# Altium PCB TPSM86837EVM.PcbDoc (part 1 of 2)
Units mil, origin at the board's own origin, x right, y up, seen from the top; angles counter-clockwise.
Board outline 3000 x 2500 mil, 4 copper layers (Top Layer, Signal Layer 1, Signal Layer 2, Bottom Layer), stack 61.2 mil thick; 63 components, 16 nets, 100 pads, 288 vias.
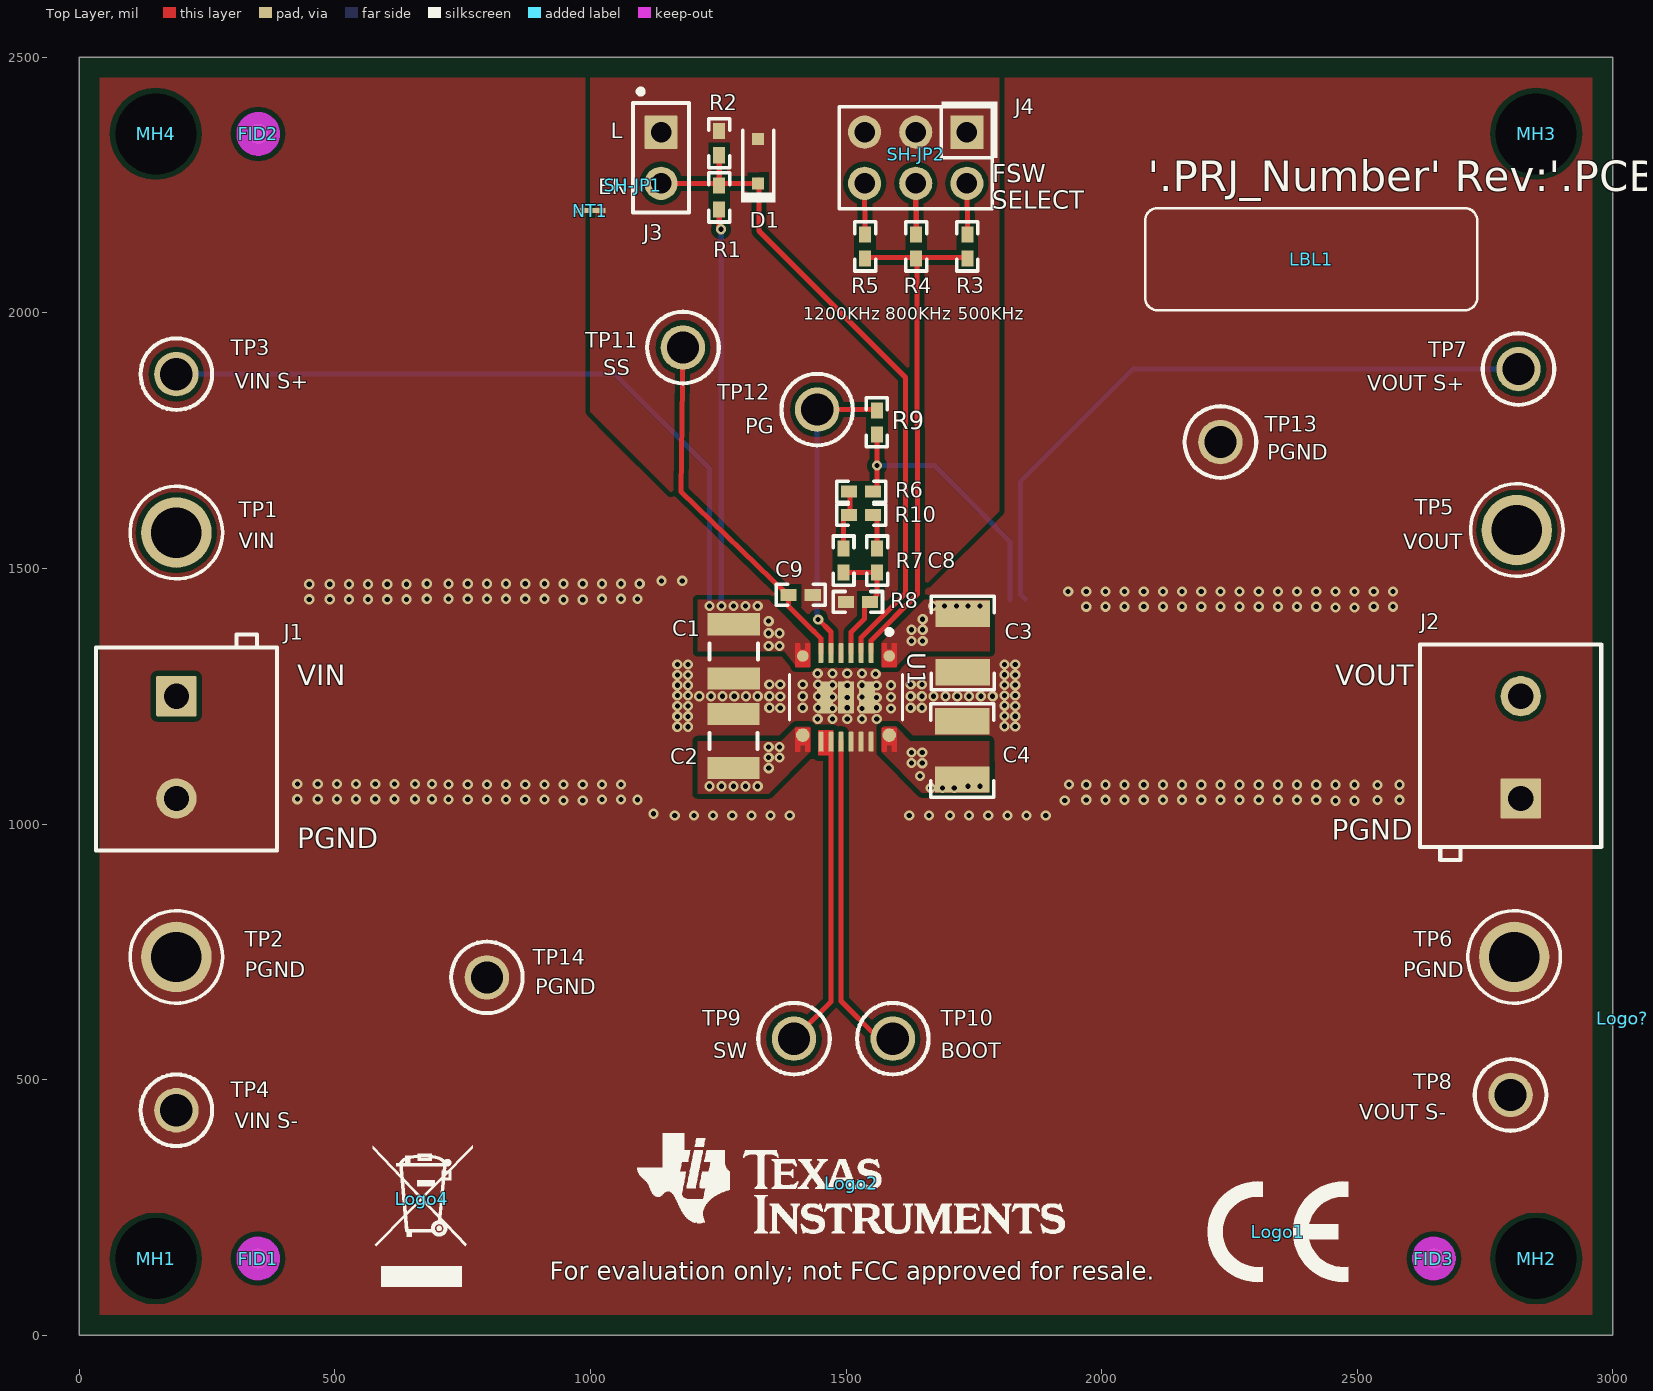
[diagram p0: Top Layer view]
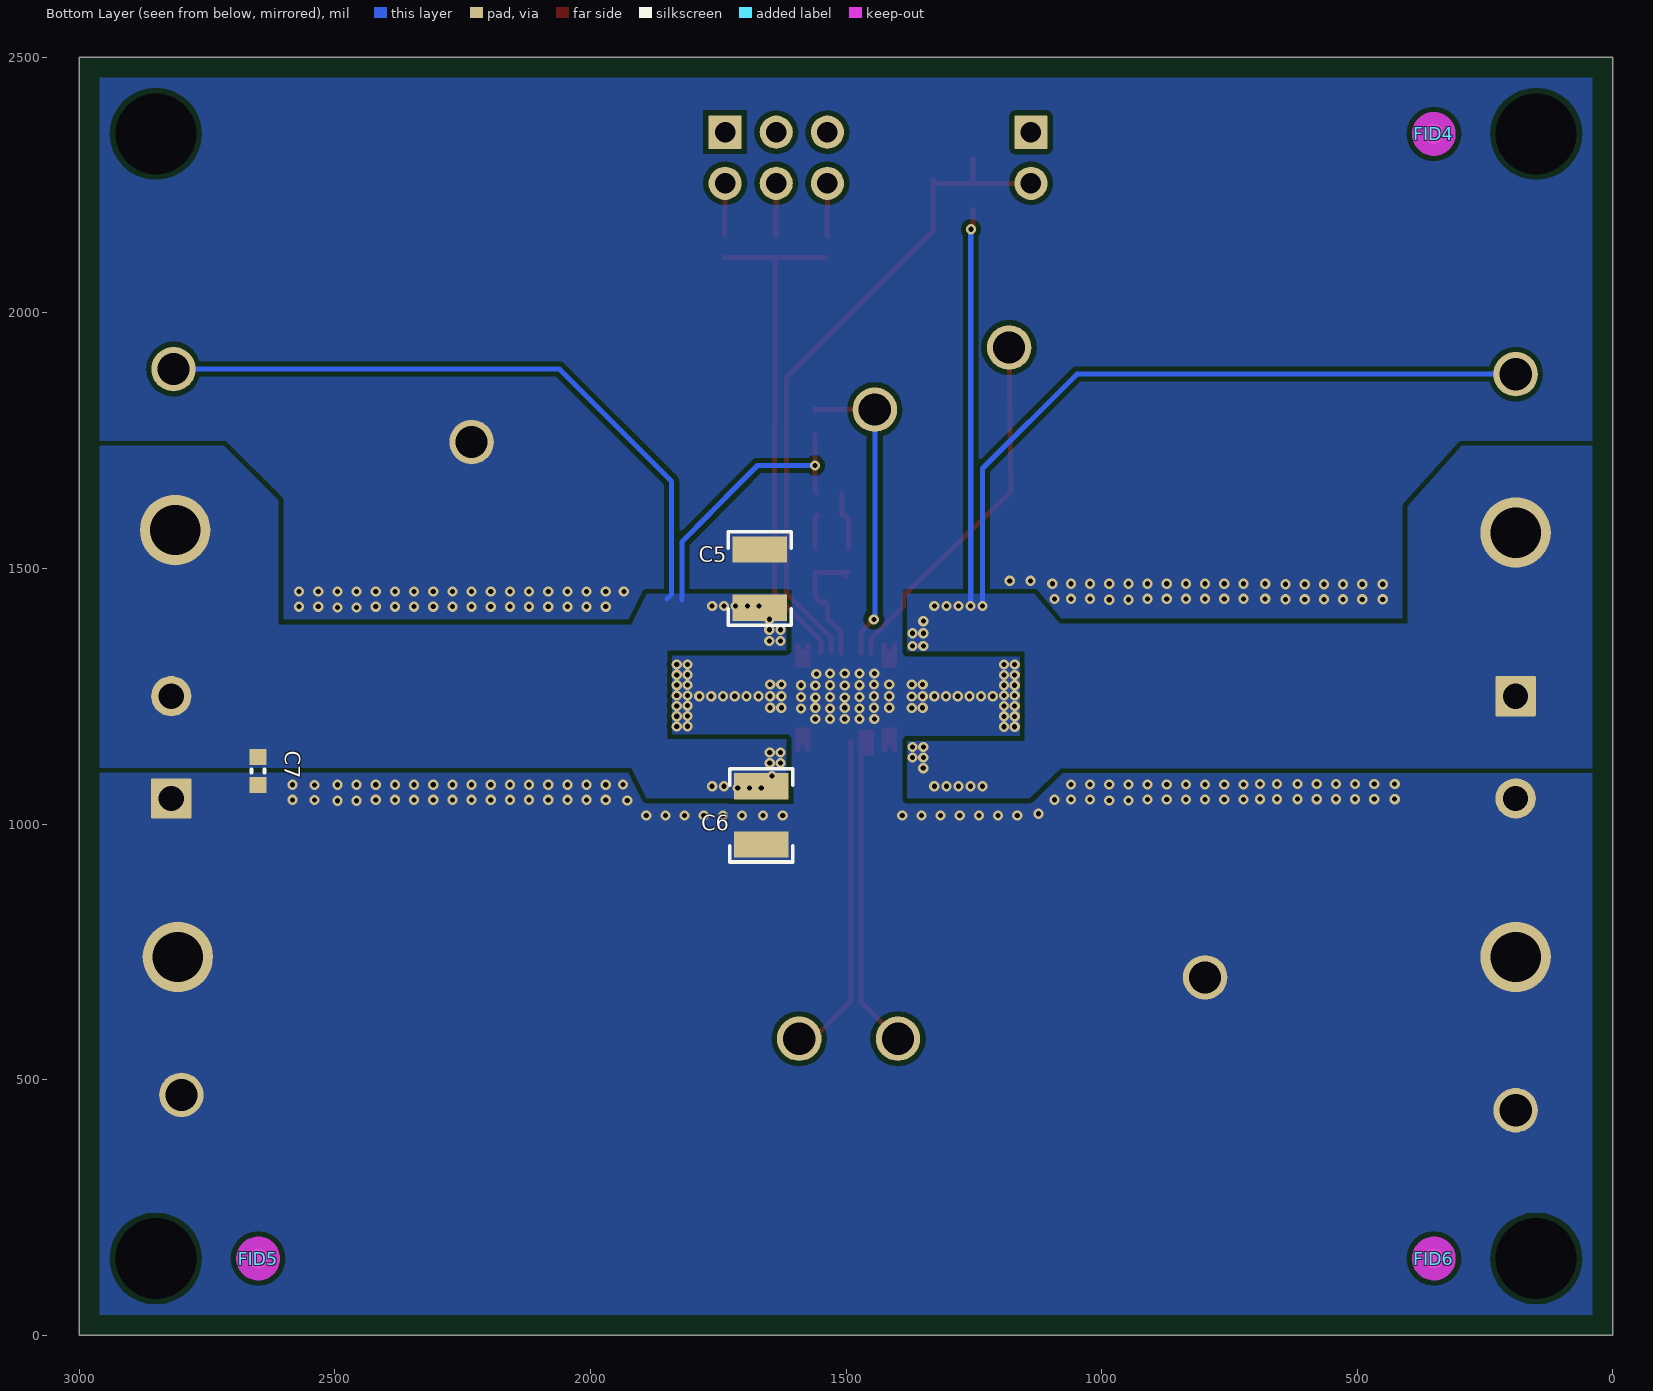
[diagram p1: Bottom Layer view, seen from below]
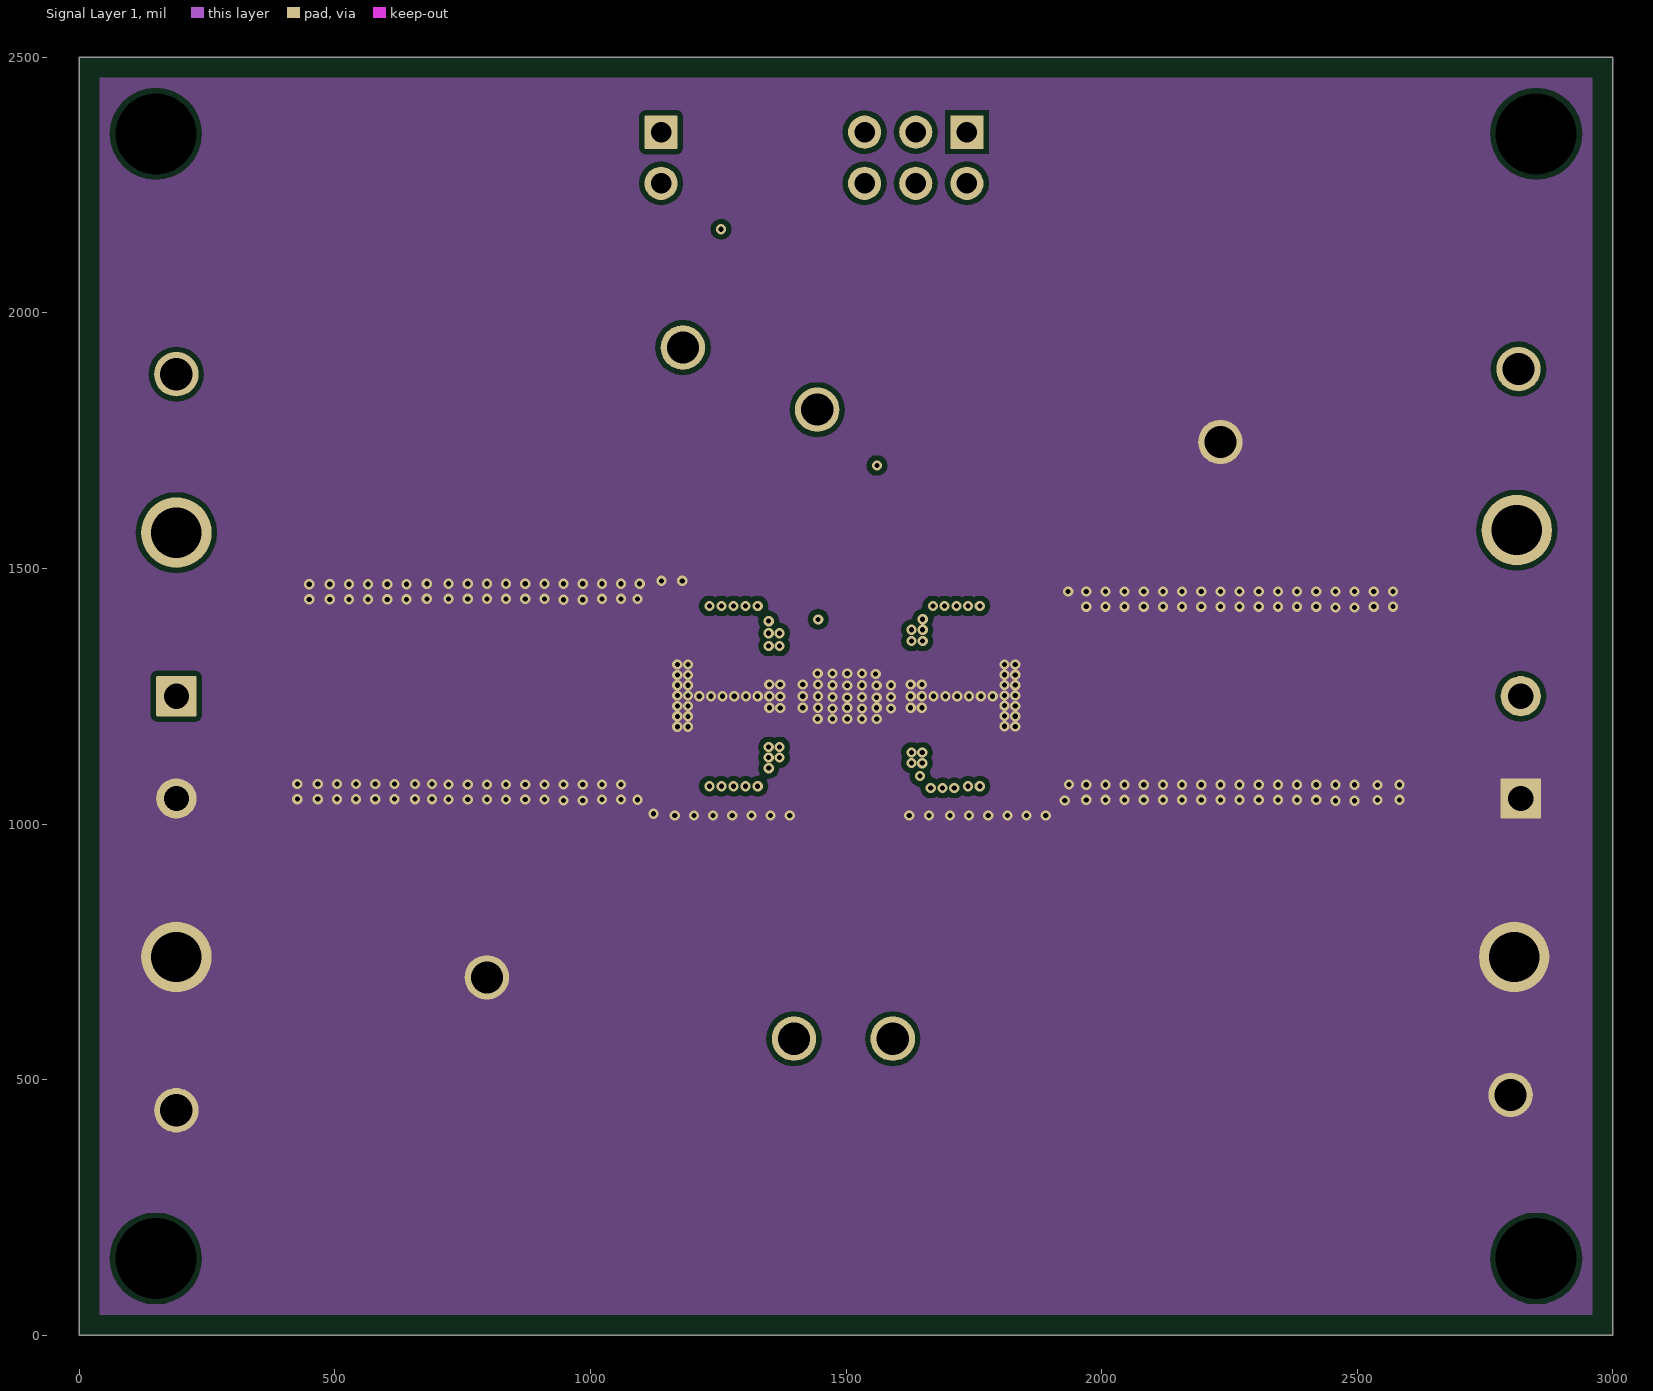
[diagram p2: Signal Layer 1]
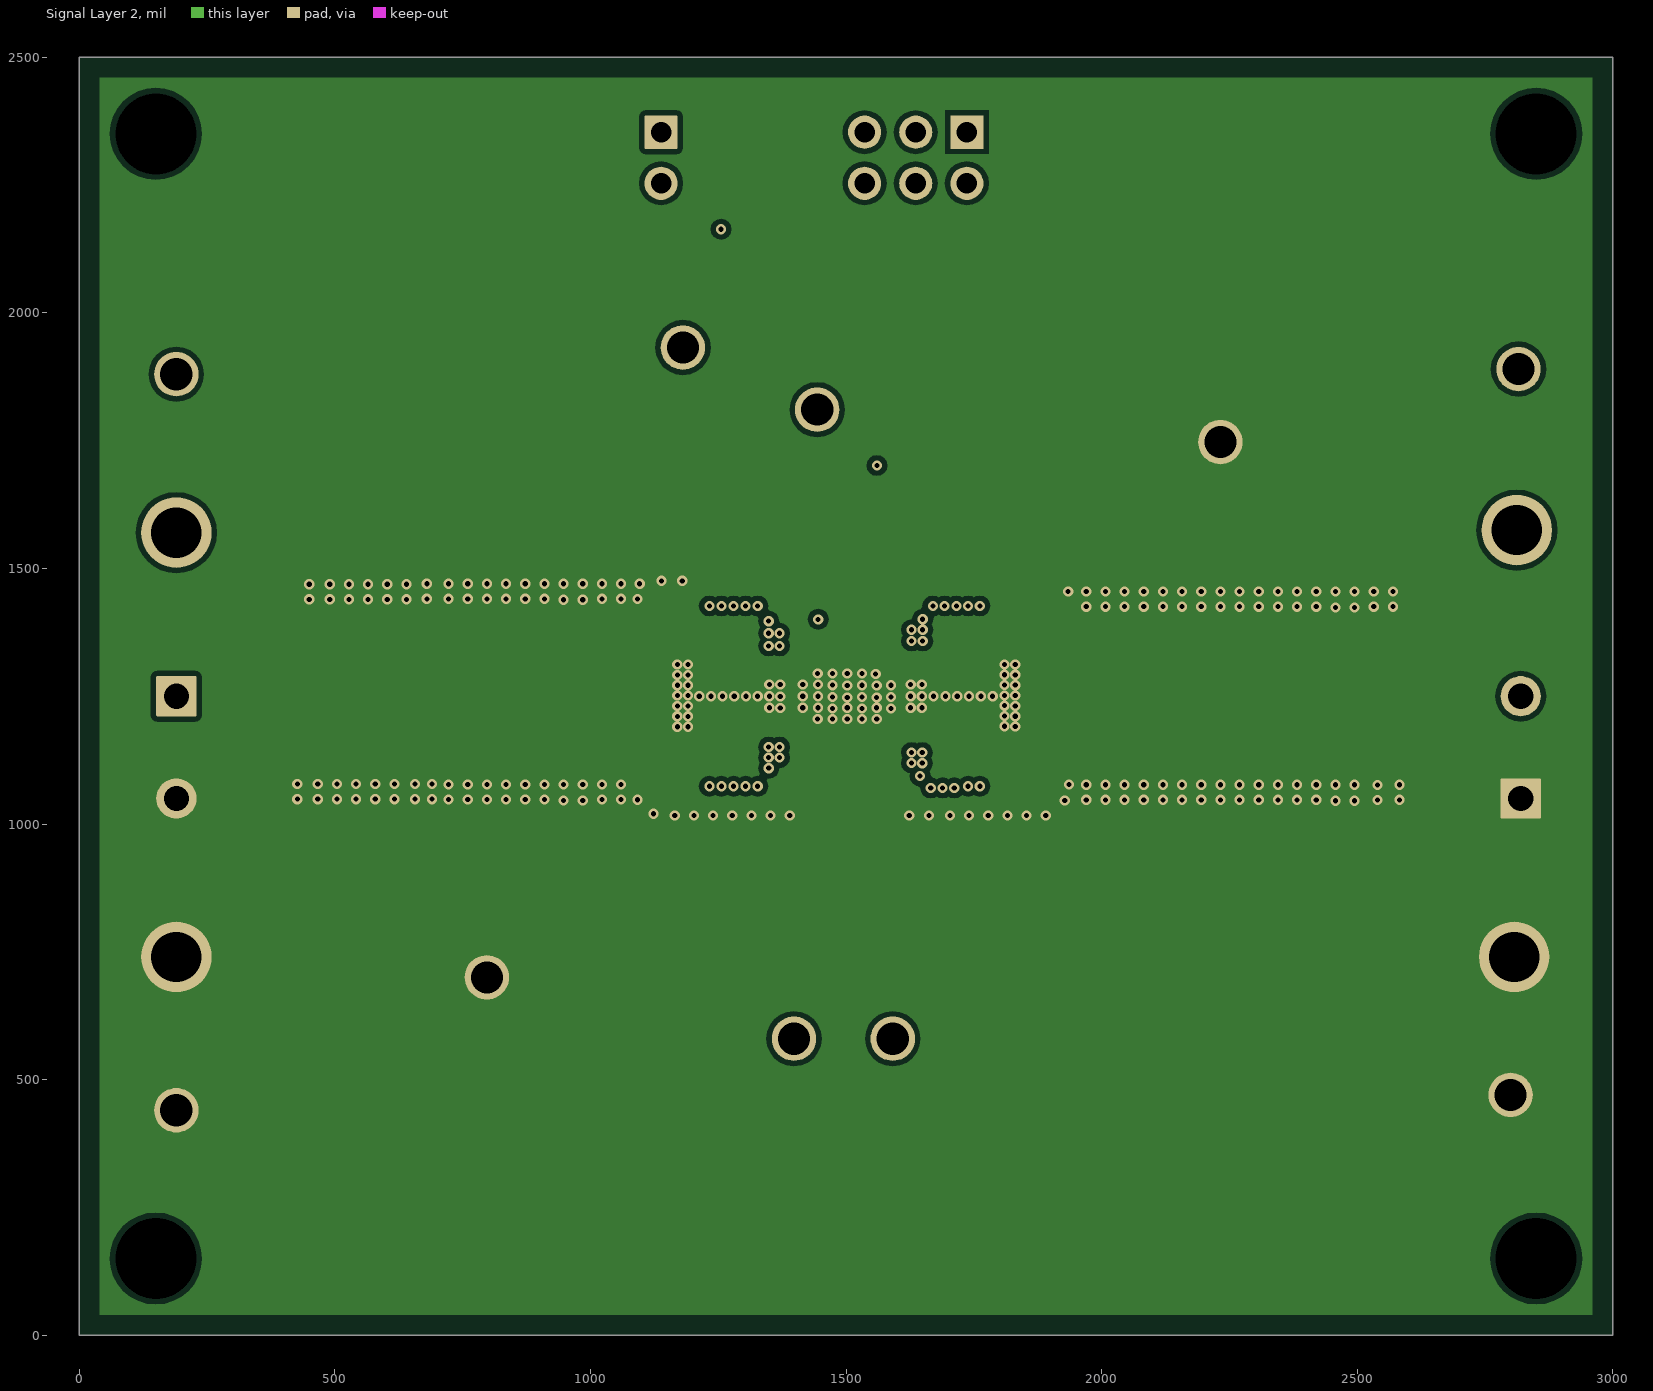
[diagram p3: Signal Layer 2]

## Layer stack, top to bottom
Top Solder: solder mask 0.4, Solder Resist, Dk 3.5
Top Layer: signal copper 2.8
Dielectric1: core 5, FR-4 High Tg, Dk 4.8
Signal Layer 1: signal copper 2.8
Dielectric3: dielectric 40, FR-4 High Tg, Dk 4.8
Signal Layer 2: signal copper 2.8
Dielectric2: dielectric 5, FR-4 High Tg, Dk 4.8
Bottom Layer: signal copper 2.8
Bottom Solder: solder mask 0.4, Solder Resist, Dk 3.5

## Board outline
0,0 3000,0 3000,2500 0,2500

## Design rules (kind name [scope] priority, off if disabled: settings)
AcuteAngle [All] p1: minimum=1.50000000000000E+0001 checktracksonly=FALSE
AssemblyTestPointUsage [All] p1: valid=2
BoardOutlineClearance BoardOutlineClearance_MountingHoles [OnCopper and InComponentClass('Mounting Holes')] p1: gap=39.37 ignorepadtopadclearanceinfootprint=FALSE
BoardOutlineClearance BoardOutlineClearance_Poly [OnCopper and IsPoly] p2: gap=40 ignorepadtopadclearanceinfootprint=FALSE
BoardOutlineClearance [OnCopper and Not InComponentClass('Logo') and not InComponentClass('FiducialMark') and not InRegion(1000,500,4000,800) and not InPoly] p3: gap=50 ignorepadtopadclearanceinfootprint=FALSE
Clearance Clearance_Keepouts [((IsTrack Or IsArc) And Not InPoly) And IsFree and IsKeepOut vs ((IsTrack Or IsArc) And Not InPoly) And IsFree and IsKeepOut] p1: gap=0 ignorepadtopadclearanceinfootprint=FALSE
Clearance Clearance_Poly [InPolygon] p2: gap=10 ignorepadtopadclearanceinfootprint=TRUE
Clearance Clearance_FiducialMark [IsKeepOut and InComponentClass('FiducialMark') vs IsPad and InComponentClass('FiducialMark')] p3: gap=0 ignorepadtopadclearanceinfootprint=FALSE
Clearance [All] p4: gap=7.87 ignorepadtopadclearanceinfootprint=TRUE
ComponentClearance ComponentClearance_MountingHoles_FiducialMarks [InComponentClass('Mounting Holes') vs InComponentClass('FiducialMark')] p1: gap=50 collisioncheckmode=3 verticalgap=10 showdistances=FALSE
ComponentClearance ComponentClearance_Shunt [InComponentClass('Header') vs InComponentClass('Shunt')] p2: gap=0 collisioncheckmode=3 verticalgap=0 showdistances=FALSE
ComponentClearance ComponentClearance_Logo [InComponentClass('Logo')] p3: gap=50 collisioncheckmode=3 verticalgap=10 showdistances=FALSE
ComponentClearance ComponentClearance_ScrewToNut [(HasFootprint('NY PMS 440 0025 PH')) vs (HasFootprint('Keystone_1902C'))] p4: gap=5 collisioncheckmode=3 verticalgap=10 showdistances=FALSE
ComponentClearance ComponentClearance_MountingHoles [InComponentClass('Mounting Holes')] p5: gap=250 collisioncheckmode=3 verticalgap=100000 showdistances=FALSE
ComponentClearance ComponentClearance_SmallPassives [HasFootprint('0201*') or HasFootprint('0402*') or HasFootprint('0508') or HasFootprint('0603*') or HasFootprint('0612') or HasFootprint('0805*') or HasFootprint('0815*') or HasFootprint('0830*') or HasFootprint('1206*') or HasFootprint('1210*') or HasFootprint('1808*') or HasFootprint('1812*') or HasFootprint('1825*') or HasFootprint('2010*') or HasFootprint('2220*') or HasFootprint('2225*') or HasFootprint('2512*') or HasFootprint('2728*') or HasFootprint('3518*') vs HasFootprint('0201*') or HasFootprint('0402*') or HasFootprint('0508') or HasFootprint('0603*') or HasFootprint('0612') or HasFootprint('0805*') or HasFootprint('0815*') or HasFootprint('0830*') or HasFootprint('1206*') or HasFootprint('1210*') or HasFootprint('1808*') or HasFootprint('1812*') or HasFootprint('1825*') or HasFootprint('2010*') or HasFootprint('2220*') or HasFootprint('2225*') or HasFootprint('2512*') or HasFootprint('2728*') or HasFootprint('3518*')] p6: gap=14.96 collisioncheckmode=3 verticalgap=10 showdistances=FALSE
ComponentClearance ComponentClearance_THtoSMT [IsThruComponent vs IsSMTComponent] p7: gap=40 collisioncheckmode=3 verticalgap=30 showdistances=FALSE
ComponentClearance ComponentClearance_THtoTH [IsThruComponent vs IsThruComponent] p8: gap=30 collisioncheckmode=3 verticalgap=30 showdistances=FALSE
ComponentClearance ComponentClearance_NetTie [HasFootprint('Net-Tie_10milWide_30milLong')] p9: gap=0 collisioncheckmode=3 verticalgap=0 showdistances=FALSE
ComponentClearance [All] p10: gap=15 collisioncheckmode=3 verticalgap=10 showdistances=FALSE
DiffPairsRouting [All] p1: maxlimit=100 minlimit=10 mostfreqgap=10 toplayer_minwidth=15 toplayer_maxwidth=15 toplayer_prefwidth=15 midlayer1_minwidth=15 midlayer1_maxwidth=15 midlayer1_prefwidth=15 midlayer2_minwidth=15 midlayer2_maxwidth=15 midlayer2_prefwidth=15 bottomlayer_minwidth=15 bottomlayer_maxwidth=15 bottomlayer_prefwidth=15 maxuncoupledlength=1000
FabricationTestPointUsage TestPointUsage [All] p1: valid=2 allowmultiple=FALSE
FabricationTestpoint Testpoint [All] p1: side=3 testpointundercomponent=TRUE minsize=40 maxsize=100 preferedsize=60 minholesize=0 maxholesize=40 preferedholesize=32 testpointgrid=1 allowsidetop=TRUE allowsidebottom=TRUE usegrid=TRUE gridtolerance=0.01
FanoutControl Fanout_LCC [IsLCC] p1: bgadir=Out bgaviamode=Centered fanoutstyle=Auto fanoutdirection=Alternating viagrid=1 // Fanout_LCC (Default Rule)
FanoutControl Fanout_BGA [IsBGA] p2: bgadir=Out bgaviamode=Centered fanoutstyle=Auto fanoutdirection=Alternating viagrid=1 // Fanout_BGA (Default Rule)
FanoutControl Fanout_Default [All] p4: bgadir=Out bgaviamode=Centered fanoutstyle=Auto fanoutdirection=Alternating viagrid=1 // Fanout_Default (Default Rule)
FanoutControl Fanout_Small [(CompPinCount < 5)] p5: bgadir=Out bgaviamode=Centered fanoutstyle=Auto fanoutdirection=OutThenIn viagrid=1 // Fanout_Small (Default Rule)
HoleSize [All] p1: absolutevalues=TRUE maxlimit=251 minlimit=7.87 maxpercent=80.000 minpercent=20.000
HoleToHoleClearance [All] p1: gap=0 allowstackedmicrovias=TRUE
MinimumAnnularRing MinimumAnnularRing_ThermalPadVias [IsVia and InAnyComponent] p1: minimumring=5
MinimumAnnularRing [All] p2: minimumring=5
MinimumSolderMaskSliver MinimumSolderMaskSliver_Logo [InComponentClass('Logo') vs InComponentClass('Logo')] p1: minsoldermaskwidth=0.7
MinimumSolderMaskSliver [All] p2: minsoldermaskwidth=0
PlaneConnect [All] p1: planeconnectstyle=Relief reliefexpansion=10 reliefentries=4 reliefconductorwidth=10 reliefairgap=10
PolygonConnect PolygonConnect_TH [IsThruPin] p1: connectstyle=Direct reliefconductorwidth=10 reliefentries=4 polygonreliefangle="90 Angle" airgapwidth=10
PolygonConnect [All] p2: connectstyle=Direct reliefconductorwidth=10 reliefentries=4 polygonreliefangle="90 Angle" airgapwidth=10
RoutingVias ThermalPadVias [IsVia and InAnyComponent] p1: holewidth=7.87 width=19.68 viastyle="Through Hole" minholewidth=7.87 minwidth=19.68 maxholewidth=12.99 maxwidth=23.62
RoutingVias [All] p2: holewidth=10 width=22 viastyle="Through Hole" minholewidth=7.87 minwidth=8 maxholewidth=40 maxwidth=65
SilkToBoardRegionClearance [Not ((IsComment or IsDesignator) And (Hide <> 'False')) and not InRegion(1000,500,4000,800)] p1:
SilkToSilkClearance SilkToSilkClearance_Pb-FreeLogo [(HasFootprint('Pb-Free_Overlay_Medium') OR HasFootprint('Pb-Free_Overlay_Small')) vs (HasFootprint('Pb-Free_Overlay_Medium') OR HasFootprint('Pb-Free_Overlay_Small'))] p1: silktosilkclearance=0
SilkToSilkClearance [All] p2: silktosilkclearance=0
SilkToSolderMaskClearance SilkToComponentPadClearance [(IsPad or IsFill or IsRegion) and InAnycomponent] p1: minsilkscreentomaskgap=0 clearancetoexposedcopper=TRUE
SilkToSolderMaskClearance "Silk to Solder Mask Opening" [All] p2: minsilkscreentomaskgap=0 clearancetoexposedcopper=FALSE
SolderMaskExpansion [All] p1: expansion=1.97 istentingtop=FALSE
UnRoutedNet [All] p1: checkbadconnections=TRUE
Width [All] p1: maxlimit=100 minlimit=6 preferedwidth=10 checkconnectedcopper=TRUE
13 further rules are at their usual default settings.

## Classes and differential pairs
component class Label: LBL1
component class Shunt: SH-JP1 SH-JP2
component class Header: J3 J4
component class TPSM86838EVM: C1 C2 C3 C4 C5 C6 C7 C8 C9 D1 J1 J2 J3 J4 NT1 R1 R2 R3 R4 R5 R6 R7 R8 R9 R10 TP1 TP2 TP3 TP4 TP5 TP6 TP7 TP8 TP9 TP10 TP11 TP12 TP13 TP14 U1
component class TPSM86838EVM_Hardware: !PCB1 FID1 FID2 FID3 FID4 FID5 FID6 H1 H2 H3 H4 H5 H6 H7 H8 LBL1 Logo1 Logo2 Logo4 Logo? MH1 MH2 MH3 MH4 SH-JP1 SH-JP2 ZZ1 ZZ2 ZZ3 ZZ4 ZZ5 ZZ6
component class Logo: Logo2
component class FiducialMark: FID1 FID2 FID3 FID4 FID5 FID6
component class AssemblyNote: ZZ1 ZZ2 ZZ3 ZZ4 ZZ5 ZZ6

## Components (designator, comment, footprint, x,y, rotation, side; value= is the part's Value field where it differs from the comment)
C1 "GRM32ER7YA106KA12L" 1210_270L 1280.34,1337.64 r90 top value=10uF
C2 "GRM32ER7YA106KA12L" 1210_270L 1280,1162.36 r270 top value=10uF
C3 "GRM32ER71E226KE15L" 1210_270 1728.49,1354.09 r270 top value=22uF
C4 "GRM32ER71E226KE15L" 1210_270 1727.37,1143.9 r90 top value=22uF
C5 "GRM32ER71E226KE15L" 1210_270 1668.84,1480.23 r90 bottom value=22uF
C6 "GRM32ER71E226KE15L" 1210_270 1665.68,1016.85 r270 bottom value=22uF
C7 "CGA3E2X7R1E104K080AA" 0603L 2650,1103.89 r270 bottom value=0.1uF
C8 "GRM1555C1H470FA01D" 0402 1561.02,1515.42 r270 top value=47pF
C9 "C1005X7R1H473K050BB" 0402 1411.24,1448.33 r0 top value=0.047uF
D1 "MMSZ5231BS-7-F" SOD-323 1328.16,2296.63 r90 top value=5.1V
FID1 "Fiducial" Fiducial10-20 350,150 r0 top
FID2 "Fiducial" Fiducial10-20 350,2350 r0 top
FID3 "Fiducial" Fiducial10-20 2650,150 r0 top
FID4 "Fiducial" Fiducial10-20 350,2350 r180 bottom
FID5 "Fiducial" Fiducial10-20 2650,150 r180 bottom
FID6 "Fiducial" Fiducial10-20 350,150 r180 bottom
J1 "ED120/2DS" On-Shore_ED120_2DS 190,1150 r270 top
J2 "ED120/2DS" On-Shore_ED120_2DS 2820,1150 r90 top
J3 "EN" TSW-102-07-X-S 1138.16,2303.33 r270 top
J4 "FSW SELECT" SULLINS_PEC03DAAN 1636.47,2303.33 r180 top
LBL1 "THT-14-423-10" Label_650x200 2410,2104.88 r180 top
Logo1 "CE Mark" CE_Mark_5mm 2345,202.26 r0 top
Logo2 "Texas Instruments" TI_Stacked_Overlay_Small 1509.88,296.77 r0 top
Logo4 "WEEE logo" WEEE_Minimum 670,267.32 r0 top
Logo? "FCC disclaimer" FCC_disclaimer 3020,620 r90 top
MH1 "MTG_NoPads" MTG_159mil 150,150 r0 top
MH2 "MTG_NoPads" MTG_159mil 2850,150 r0 top
MH3 "MTG_NoPads" MTG_159mil 2850,2350 r0 top
MH4 "MTG_NoPads" MTG_159mil 150,2350 r0 top
NT1 "Net-Tie" Net-Tie_10milWide_30milLong 1000,2200 r180 top net-tie
R1 "CRCW0402169KFKED" 0402 1251.94,2225.63 r270 top value=169k
R2 "TNPW040236K1BEED" 0402 1251.94,2331.9 r270 top value=36.1k
R3 "RC0402FR-0730K1L" 0402 1737.34,2129.88 r270 top value=30.1k
R4 "CRCW0402162KFKED" 0402 1637.34,2129.88 r270 top value=162k
R5 "CRCW0402374KFKED" 0402 1537.34,2129.88 r270 top value=374k
R6 "RC0402FR-0749R9L" 0402 1529.53,1650.13 r0 top value=49.9
R7 "CRCW040220K0FKED" 0402 1495.19,1515.42 r90 top value=20.0k
R8 "CRCW040210K0FKED" 0402 1523.41,1434.34 r0 top value=10.0k
R9 "RC1005F104CS" 0402 1560.46,1785.6 r270 top value=100k
R10 "CRCW04020000Z0ED" 0402 1529.53,1604.84 r180 top value=0
SH-JP1 "SNT-100-BK-G" SNT-100-BK-G 1083.16,2249.26 r180 top value=1x2
SH-JP2 "SNT-100-BK-G" SNT-100-BK-G 1636.47,2310.48 r90 top value=1x2
TP1 "VIN" Keystone1502-2 190,1570 r0 top
TP2 "PGND" Keystone1502-2 190,740 r0 top
TP3 "VIN S+" Keystone5010 190,1880 r0 top
TP4 "VIN S-" Keystone5011 190,440 r0 top
TP5 "Vout" Keystone1502-2 2812.26,1575 r0 top
TP6 "PGND" Keystone1502-2 2807.11,740 r0 top
TP7 "VOUT S+" Keystone5010 2815.58,1890 r0 top
TP8 "VOUT S-" Keystone5011 2800.04,470 r0 top
TP9 "SW" Keystone5010 1398.27,580 r0 top
TP10 "BOOT" Keystone5010 1591.5,580 r0 top
TP11 "SS" Keystone5010 1181.01,1932.12 r0 top
TP12 "PG" Keystone5010 1443.64,1810.59 r0 top
TP13 "PGND" Keystone5011 2232.5,1747.21 r0 top
TP14 "PGND" Keystone5011 797.5,700 r0 top
U1 "TPSM86837RCGR" RCG0019A-MFG 1500.04,1247.7 r270 top
ZZ1 "This Assembly Note is for PCB labels only" AssemblyNoteLabel 183.32,3180 r0 top
ZZ2 "These assemblies must be clean and free from flux and all contaminants. Use of no clean flux is not acceptable." AssemblyNote 178.91,3089.12 r0 top
ZZ3 "These assemblies must comply with workmanship standards IPC-A-610 Class 2, unless otherwise specified." AssemblyNote 178.91,2996.6 r0 top
ZZ4 "Place SH-J1 on J3 pins 3 and 4" AssemblyNote 178.91,2904.08 r0 top
ZZ5 "Place SH-J2 on J4 pins 5 and 6" AssemblyNote 178.91,2811.56 r0 top
ZZ6 "Place SH-J3 on J5 pins 6 and 7" AssemblyNote 178.91,2719.04 r0 top

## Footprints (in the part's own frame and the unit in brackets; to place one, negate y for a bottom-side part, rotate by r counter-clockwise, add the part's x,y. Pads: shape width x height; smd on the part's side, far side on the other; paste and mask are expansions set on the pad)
0402 [mm] "0402 from SM-752 data"
  rect 0.8x0.6 smd: 1(-0.6,0) 2(0.6,0)
  silkscreen extent -1.22,-0.52 1.22,0.52, body extent -0.55,-0.3 0.55,0.3, height 0.6
0603L [mm] "0603 from SM-752 data"
  rect 0.8x0.85 smd: 1(-0.7,0) 2(0.7,0)
  silkscreen extent -0.07,-0.33 0.07,0.33, body extent -0.87,-0.47 0.87,0.47, height 1
1210_270 [mm] "1210"
  rect 1.3x2.7 smd: 1(-1.45,0) 2(1.45,0)
  silkscreen extent -2.32,-1.57 2.32,1.57, body extent -1.7,-1.35 1.7,1.35, height 2.7
1210_270L [mm] "1210"
  rect 1.1x2.6 smd: 1(-1.35,0) 2(1.35,0)
  silkscreen extent -0.4,-1.2 0.4,1.2, body extent -1.7,-1.35 1.7,1.35, height 2.7
AssemblyNote [mil] "Assembly Note"
AssemblyNoteLabel [mil] "Assembly Note for PCB Labels"
CE_Mark_5mm [mil] "Minimum text height for CE Mark"
  silkscreen extent -138,-98 138,98
FCC_disclaimer [mil]
Fiducial10-20 [mm]
  round 1 smd mask+0.5: 1(0,0)
  Top Layer keep-out circle w1.178: c0,0 r0.5
Keystone1502-2 [mm] "Double Turret"
  round 3.5 hole 2.5: 1(0,0)
  silkscreen extent -2.3,-2.3 2.3,2.3, body extent -1.6,-1.6 1.59,1.6, height 5.62
Keystone5010 [mil] "Keystone Multipurpose loops"
  round 87 hole 63: 1(0,0)
  silkscreen extent -70,-70 70,70, body extent -63,-63 63,62, height 319
Keystone5011 [mil] "Keystone Multipurpose loops"
  round 87 hole 63: 1(0,0)
  silkscreen extent -70,-70 70,70, body extent -63,-63 63,62, height 319
Label_650x200 [mil] "Thermal Transfer Label"
  round 1 on Mech13: 0(0,0)
  silkscreen extent -325,-100 325,100, body extent -325,-100 325,100, height 1
MTG_159mil [mil] "159mil Non Plated Hole"
  round 150 hole 159 unplated: 1(0,0)
Net-Tie_10milWide_30milLong [mil] "10mil net tie, no solder mask opening, no solder paste"
  rect 30x10 smd paste-5 mask-5: 1(-15,0) 2(15,0)
On-Shore_ED120_2DS [mm] "ONSHORE"
  rrect5% 2x2 hole 1.25: 1(-2.54,0)
  round 2 hole 1.25: 2(2.54,0)
  silkscreen extent -5.6,-4 5.12,5, body extent -5.78,-4 5.08,5, height 13
RCG0019A-MFG [mm]
  round 0.573 smd paste-1000 mask+0: 1(-2.057,2.15) 8(-2.057,-2.15)
  rrect40% 1x0.25 smd paste+0 mask+0: 2(-2.2,1.25) 3(-2.2,0.75) 4(-2.2,0.25) 5(-2.2,-0.25) 6(-2.2,-0.75) 7(-2.2,-1.25) 10(2.2,-1.25) 11(2.2,-0.75) 12(2.2,-0.25) 13(2.2,0.25) 14(2.2,0.75) 15(2.2,1.25)
  round 0.675 smd paste-1000 mask+0: 9(1.876,-2.15) 16(1.876,2.15)
  rrect13% 1.6x0.8 smd paste-1000 mask+0: 17(0,1.05) 18(0,0) 19(0,-1.05)
  Top Layer region: -2.65,-2.525 -2.669,-2.521 -2.685,-2.51 -2.696,-2.494 -2.7,-2.475 -2.7,-2.475 -2.7,-2.325 -2.693,-2.3 -2.675,-2.282 -2.65,-2.275 -2.65,-2.275 -2.402,-2.275 -2.385,-2.261 -2.375,-2.241 -2.375,-2.241 -2.375,-2.058 -2.379,-2.041 -2.392,-2.029 -2.408,-2.025 -2.408,-2.025 -2.651,-2.025 -2.67,-2.021 -2.686,-2.01 -2.697,-1.994 -2.701,-1.975 -2.701,-1.975 -2.701,-1.825 -2.694,-1.8 -2.676,-1.782 -2.651,-1.775 -2.651,-1.775 -1.551,-1.775 -1.526,-1.782 -1.508,-1.8 -1.501,-1.825 -1.501,-1.825 -1.501,-2.475 -1.505,-2.494 -1.516,-2.51 -1.532,-2.521 -1.551,-2.525 -1.551,-2.525
  Top Layer region: -2.65,1.775 -2.669,1.779 -2.685,1.79 -2.696,1.806 -2.7,1.825 -2.7,1.825 -2.7,1.975 -2.693,2 -2.675,2.018 -2.65,2.025 -2.65,2.025 -2.402,2.025 -2.385,2.039 -2.375,2.059 -2.375,2.059 -2.375,2.242 -2.379,2.258 -2.392,2.271 -2.408,2.275 -2.408,2.275 -2.651,2.275 -2.67,2.279 -2.686,2.29 -2.697,2.306 -2.701,2.325 -2.701,2.325 -2.701,2.475 -2.694,2.5 -2.676,2.518 -2.651,2.525 -2.651,2.525 -1.551,2.525 -1.526,2.518 -1.508,2.5 -1.501,2.475 -1.501,2.475 -1.501,1.825 -1.505,1.806 -1.516,1.79 -1.532,1.779 -1.551,1.775 -1.551,1.775
  Top Layer region: 2.65,1.775 2.669,1.779 2.685,1.79 2.696,1.806 2.7,1.825 2.7,1.825 2.7,1.975 2.693,2 2.675,2.018 2.65,2.025 2.65,2.025 2.402,2.025 2.385,2.039 2.375,2.059 2.375,2.059 2.375,2.242 2.379,2.258 2.392,2.271 2.408,2.275 2.408,2.275 2.651,2.275 2.67,2.279 2.686,2.29 2.697,2.306 2.701,2.325 2.701,2.325 2.701,2.475 2.694,2.5 2.676,2.518 2.651,2.525 2.651,2.525 1.551,2.525 1.526,2.518 1.508,2.5 1.501,2.475 1.501,2.475 1.501,1.825 1.505,1.806 1.516,1.79 1.532,1.779 1.551,1.775 1.551,1.775
  Top Layer region: 2.65,-2.525 2.669,-2.521 2.685,-2.51 2.696,-2.494 2.7,-2.475 2.7,-2.475 2.7,-2.325 2.693,-2.3 2.675,-2.282 2.65,-2.275 2.65,-2.275 2.402,-2.275 2.385,-2.261 2.375,-2.241 2.375,-2.241 2.375,-2.058 2.379,-2.041 2.392,-2.029 2.408,-2.025 2.408,-2.025 2.651,-2.025 2.67,-2.021 2.686,-2.01 2.697,-1.994 2.701,-1.975 2.701,-1.975 2.701,-1.825 2.694,-1.8 2.676,-1.782 2.651,-1.775 2.651,-1.775 1.551,-1.775 1.526,-1.782 1.508,-1.8 1.501,-1.825 1.501,-1.825 1.501,-2.475 1.505,-2.494 1.516,-2.51 1.532,-2.521 1.551,-2.525 1.551,-2.525
  silkscreen extent -3.37,-2.8 1.13,2.8, body extent -2.8,-2.9 2.8,2.9, height 0.25
SNT-100-BK-G [mil] "Samtec STEP model"
  round 1 on Mech3: 0(0,0)
  body extent -100,-50 100,50, height 344
SOD-323 [mm] "NXP recommended land pattern"
  rect 0.6x0.6 smd paste-0.05: 1(-1.1,0) 2(1.1,0)
  silkscreen extent -2.06,-0.86 1.53,0.86, body extent -1.3,-0.67 1.3,0.68, height 1.1
SULLINS_PEC03DAAN [mm] "SULLINS"
  rect 1.65x1.65 hole 1.016 mask+0: 1(-2.54,-1.27)
  round 1.65 hole 1.016 mask+0: 2(-2.54,1.27) 3(0,-1.27) 4(0,1.27) 5(2.54,-1.27) 6(2.54,1.27)
  silkscreen extent -4.06,-2.79 3.81,2.54, body extent -3.81,-2.54 3.81,2.54, height 8.38
TI_Stacked_Overlay_Small [mil]
  silkscreen extent -418,-98 418,98
TSW-102-07-X-S [mm] "Samtec 100 mil 1x2 head, 230 mil above insulator"
  rrect6% 1.65x1.65 hole 1.016: 1(-1.27,0)
  round 1.65 hole 1.016: 2(1.27,0)
  silkscreen extent -3.42,-1.4 2.72,1.4, body extent -2.54,-1.27 2.54,1.27, height 8.38
WEEE_Minimum [mil] "WEEElie bin"
  silkscreen extent -95,-172 99,104

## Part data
C1 C2: library part CMP-0009233-2, "CAP, CERM, 10 uF, 35 V, +/- 10%, X7R, 1210", Cap_Case=1210, Manufacturer=MuRata, Supplier Part Number 1=490-5314-1-ND, TempCo=X7R, Tolerance_%=10%, Value1=Unknown, Value2=35V, ValueDisplayed=10uF
C3 C4 C5 C6: library part CMP-0009224-2, "CAP, CERM, 22 uF, 25 V, +/- 10%, X7R, 1210", Cap_Case=1210, Manufacturer=MuRata, Supplier Part Number 1=490-5313-1-ND, TempCo=X7R, Tolerance_%=10%, Value1=Unknown, Value2=25V, ValueDisplayed=22uF
C7: library part CMP-0007077-5, "CAP, CERM, 0.1 uF, 25 V, +/- 10%, X7R, AEC-Q200 Grade 1, 0603", Cap_Case=0603, Manufacturer=TDK, Supplier Part Number 1=445-5667-1-ND, TempCo=X7R, Tolerance_%=10%, Value1=Unknown, Value2=25V, ValueDisplayed=0.1uF
C8: library part CMP-0006467-2, "CAP, CERM, 47 pF, 50 V, +/- 1%, C0G/NP0, 0402", Cap_Case=0402, Manufacturer=MuRata, Supplier Part Number 1=490-6241-1-ND, TempCo=C0G/NP0, Tolerance_%=1%, Value1=Unknown, Value2=50V, ValueDisplayed=47pF
C9: library part CMP-0006298-2, "CAP, CERM, 0.047 uF, 50 V, +/- 10%, X7R, 0402", Cap_Case=0402, Manufacturer=TDK, Supplier Part Number 1=445-7336-1-ND, TempCo=X7R, Tolerance_%=10%, Value1="0.06407 ohm", Value2=50V, ValueDisplayed=0.047uF
D1: library part CMP-0005854-3, "Diode, Zener, 5.1 V, 200 mW, SOD-323", Manufacturer="Diodes Inc.", Power_W=200mW, Value1=0.2W
FID1 FID2 FID3 FID4 FID5 FID6: library part CMP-0077181-1, "Fiducial mark.  There is nothing to buy or mount.", Manufacturer=N/A
J1 J2: library part CMP-0074910-1, "Terminal Block, 5.08 mm, 2x1, Brass, TH", Color=Blue, Current_A=15A, Manufacturer="On-Shore Technology", Supplier Part Number 1=ED1609-ND, Voltage_V=300V
J3: library part CMP-0075405-1, "Header, 100mil, 2x1, Gold, TH", Color=Black, Current_A=6.3A, Manufacturer=Samtec, PartNumber=TSW-102-07-G-S, Supplier Part Number 1=SAM1029-02-ND, Voltage_V=550V
J4: library part CMP-0054552-2, "Header, 100mil, 3x2, Tin, TH", Color=Black, Current_A=3A, Manufacturer="Sullins Connector Solutions", PartNumber=PEC03DAAN, Supplier Part Number 1=S2012E-03-ND, Voltage_V=1.8kV
LBL1: library part CMP-0003625-1, "Thermal Transfer Printable Labels, 0.650\" W x 0.200\" H - 10,000 per roll", Manufacturer=Brady, Supplier Part Number 1=97C5133
Logo1: library part CMP-0074844-1
Logo2: library part CMP-0074838-1, "Texas Instrument Corporate Signature"
Logo4: library part CMP-0074769-1
Logo?: library part CMP-0074847-1, "FCC_disclaimer"
MH1 MH2 MH3 MH4: library part CMP-0078424-2, "PCB Mounting Hole, No Pad", Manufacturer=Any, PartNumber=N/A
NT1: library part CMP-0078142-4, "Single point connection between nets.", Manufacturer=N/A
R1: library part CMP-0026038-1, "RES, 169 k, 1%, 0.063 W, 0402", Manufacturer=Vishay-Dale, Power_W=63mW, Supplier Part Number 1=541-169KLCT-ND, TempCo="100 ppm/C", Tolerance_%=1%, Value2=0.063W, Value_Code=169k
R2: library part CMP-0026820-1, "RES, 36.1 k, 0.1%, 0.063 W, AEC-Q200 Grade 1, 0402", Manufacturer=Vishay-Dale, Power_W=63mW, Supplier Part Number 1=541-2123-1-ND, TempCo="25 ppm/C", Tolerance_%=0.1%, Value2=0.063W, Value_Code=36k1, ValueDisplayed=36.1k
R3: library part CMP-0026730-1, "RES, 30.1 k, 1%, 0.063 W, 0402", Manufacturer="Yageo America", Power_W=63mW, Supplier Part Number 1=311-30.1KLRCT-ND, TempCo="100 ppm/C", Tolerance_%=1%, Value2=0.063W, Value_Code=30k1, ValueDisplayed=30.1k
R4: library part CMP-0026034-3, "RES, 162 k, 1%, 0.063 W, AEC-Q200 Grade 0, 0402", Manufacturer=Vishay-Dale, Power_W=63mW, Supplier Part Number 1=541-162KLCT-ND, TempCo="100 ppm/C", Tolerance_%=1%, Value2=0.063W, Value_Code=162k
R5: library part CMP-0026317-2, "RES, 374 k, 1%, 0.063 W, AEC-Q200 Grade 0, 0402", Manufacturer=Vishay-Dale, Power_W=63mW, Supplier Part Number 1=541-374KLCT-ND, TempCo="100 ppm/C", Tolerance_%=1%, Value2=0.063W, Value_Code=374k
R6: library part CMP-0026738-1, "RES, 49.9, 1%, 0.063 W, 0402", Manufacturer="Yageo America", Power_W=63mW, Supplier Part Number 1=311-49.9LRCT-ND, TempCo="100 ppm/C", Tolerance_%=1%, Value2=0.063W, Value_Code=49R9, ValueDisplayed=49.9
R7: library part CMP-0026162-2, "RES, 20.0 k, 1%, 0.063 W, AEC-Q200 Grade 0, 0402", Manufacturer=Vishay-Dale, Power_W=63mW, Supplier Part Number 1=541-20.0KLCT-ND, TempCo="100 ppm/C", Tolerance_%=1%, Value2=0.063W, Value_Code=20k0, ValueDisplayed=20.0k
R8: library part CMP-0025958-3, "RES, 10.0 k, 1%, 0.063 W, AEC-Q200 Grade 0, 0402", Manufacturer=Vishay-Dale, Power_W=63mW, Supplier Part Number 1=541-10.0KLCT-ND, TempCo="100 ppm/C", Tolerance_%=1%, Value2=0.063W, Value_Code=10k0, ValueDisplayed=10.0k
R9: library part CMP-0026745-1, "RES, 100 k, 1%, 0.063 W, 0402", Manufacturer="Samsung Electro-Mechanics", Power_W=63mW, Supplier Part Number 1=1276-3432-1-ND, TempCo="100 ppm/C", Tolerance_%=1%, Value2=0.063W, Value_Code=100k
R10: library part CMP-0026822-1, "RES, 0, 5%, 0.063 W, 0402", Manufacturer=Vishay-Dale, Power_W=63mW, Supplier Part Number 1=541-0.0JCT-ND, TempCo="200 ppm/C", Tolerance_%=5%, Value2=0.063W, Value_Code=0000, ValueDisplayed=0
SH-JP1 SH-JP2: library part CMP-0003623-3, "Shunt, 100mil, Gold plated, Black", Alternate Manufacturer=3M, Alternate PartNumber=969102-0000-DA, Manufacturer=Samtec, Supplier Part Number 1=SAM8858-ND
TP1 TP2 TP5 TP6: library part CMP-0055113-1, "Terminal, Turret, TH, Double", Manufacturer=Keystone, PartNumber=1502-2, Supplier Part Number 1=36-1502-2-ND
TP3 TP7 TP9 TP10 TP11 TP12: library part CMP-0055147-1, "Test Point, Multipurpose, Red, TH", Color=Red, Manufacturer=Keystone, PartNumber=5010, Supplier Part Number 1=36-5010-ND
TP4 TP8 TP13 TP14: library part CMP-0055148-1, "Test Point, Multipurpose, Black, TH", Color=Black, Manufacturer=Keystone, PartNumber=5011, Supplier Part Number 1=36-5011-ND
U1: library part CMP-0121040-3, "4.5V - 28V, 8A Buck Power Module", Manufacturer="Texas Instruments", Operating Temperature Range=to
ZZ1: library part CMP-0003616-3
ZZ2: library part CMP-0077237-1
ZZ3: library part CMP-0077238-1
ZZ4 ZZ5 ZZ6: library part CMP-0003615-1, "This Assembly Note will show in the PcbDoc and associated outputs"

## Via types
v1: diameter 20, hole 10, Top Layer to Bottom Layer, 288 vias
